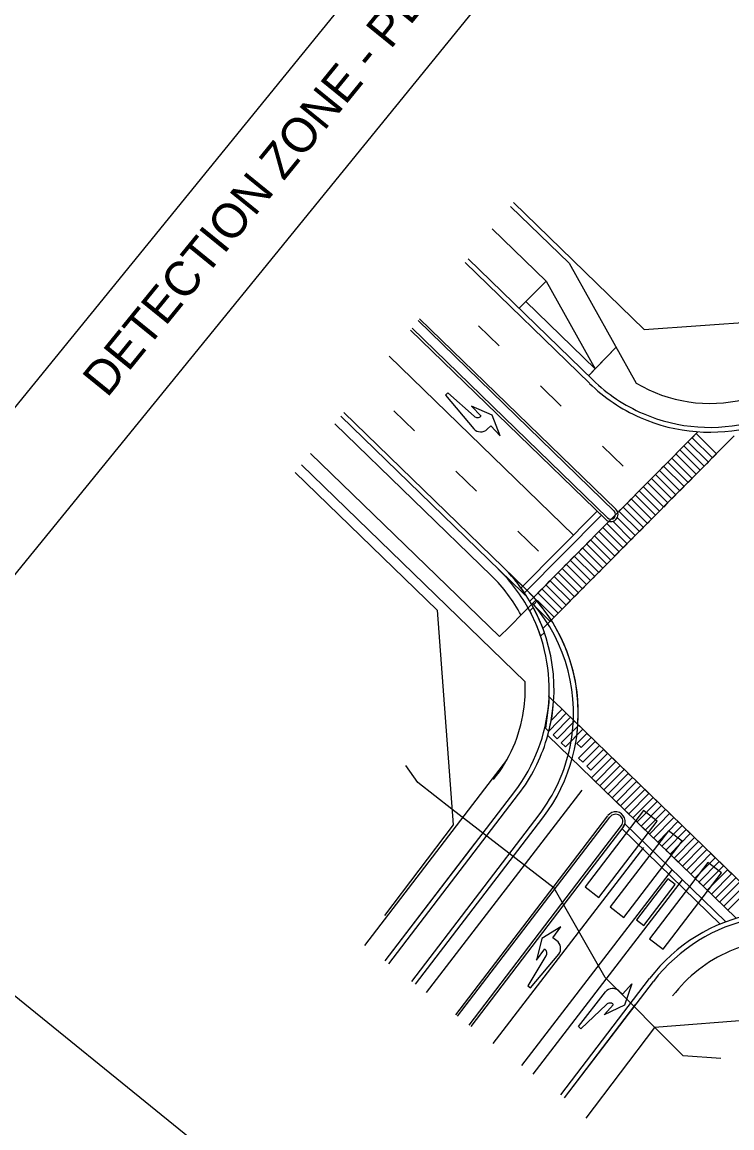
# Model space of a CAD drawing. Extents: x 592613 to 600223, y 4837996 to 4840103.
# Drawn here: x 592701.09 to 592719.57, y 4838932.93 to 4838961.75 of the extents above; entities that cross this region are included whole.
import ezdxf

# ---------------------------------------------------------------- set-up
doc = ezdxf.new("R2010")
doc.units = 0
for name, color, linetype in [('ENG_BORDER', 7, 'Continuous'), ('ENG_BUS-PAD', 7, 'Continuous'), ('ENG_CURB-BACK', 7, 'Continuous'), ('ENG_CURBSTOP', 7, 'Continuous'), ('ENG_EPAVT', 7, 'Continuous'), ('ENG_KILLSTRIP', 7, 'Continuous'), ('ENG_LANEWAY', 7, 'Continuous'), ('ENG_MULTI-TRAIL', 7, 'Continuous'), ('ENG_SH_RIPRAP', 7, 'Continuous'), ('ENG_SIDEWALK', 7, 'Continuous'), ('ENG_TITLEBLOCK', 7, 'Continuous'), ('ENG_TX_TITLEBLOCK', 7, 'Continuous'), ('Level 11', 7, 'Continuous'), ('Level 12', 7, 'Continuous'), ('PMK_LANE', 7, 'Continuous'), ('PMK_LANE_3-6', 7, 'Continuous'), ('ROW_ENG_ROW', 7, 'Continuous')]:
    doc.layers.add(name, color=color, linetype=linetype)

msp = doc.modelspace()

# ---------------------------------------------------------------- linework, layer by layer
at = {"layer": 'ENG_BORDER'}
msp.add_lwpolyline([(592658.479, 4838970.843), (592762.862, 4838886.033)], dxfattribs=at)
at = {"layer": 'ENG_BUS-PAD'}
for p, q in [((592714.73, 4838955.003), (592713.331, 4838956.363)), ((592714.026, 4838954.293), (592714.73, 4838955.003))]:
    msp.add_line(p, q, dxfattribs=at)
at = {"layer": 'ENG_CURB-BACK'}
for p, q in [((592715.946, 4838952.427), (592712.7, 4838955.581)), ((592716.329, 4838948.831), (592711.24, 4838953.775)), ((592716.504, 4838949.01), (592711.398, 4838953.971)), ((592714.119, 4838946.883), (592709.386, 4838951.481)), ((592710.54, 4838937.284), (592713.916, 4838941.704)), ((592711.236, 4838936.753), (592714.548, 4838941.09)), ((592715.454, 4838939.806), (592716.391, 4838941.033)), ((592715.672, 4838939.474), (592716.693, 4838940.811)), ((592712.428, 4838935.842), (592715.454, 4838939.806)), ((592712.726, 4838935.615), (592715.672, 4838939.473)), ((592715.21, 4838933.719), (592717.525, 4838936.751))]:
    msp.add_line(p, q, dxfattribs=at)
for centre, radius, start, end in [((592718.995, 4838955.565), 4.375, 246.6005, 322.6377), ((592718.995, 4838955.565), 4.375, 225.8289, 246.6005), ((592716.416, 4838948.921), 0.125, 315.8289, 45.8289), ((592716.416, 4838948.921), 0.125, 225.8289, 315.8289), ((592710.438, 4838944.359), 4.375, 27.9119, 45.8289), ((592710.438, 4838944.359), 4.125, 28.0452, 45.829), ((592711.07, 4838943.745), 4.375, 44.5335, 45.8289), ((592711.07, 4838943.745), 4.375, 348.3699, 40.8056), ((592710.438, 4838944.359), 4.375, 322.6377, 27.9119), ((592711.07, 4838943.745), 4.375, 322.6377, 348.3699), ((592716.541, 4838940.92), 0.187, 324.4115, 142.9443), ((592721.003, 4838934.096), 4.375, 60.4988, 142.6377)]:
    msp.add_arc(centre, radius, start, end, dxfattribs=at)
at = {"layer": 'ENG_CURBSTOP'}
for points in [[(592714.587, 4838945.747), (592714.686, 4838945.846), (592714.619, 4838946.023), (592714.563, 4838946.159), (592714.507, 4838946.281), (592714.426, 4838946.443), (592714.398, 4838946.498), (592714.398, 4838946.498), (592714.307, 4838946.406), (592714.34, 4838946.327), (592714.459, 4838946.083), (592714.545, 4838945.869)], [(592714.713, 4838943.355), (592714.802, 4838943.268), (592714.885, 4838943.667), (592714.918, 4838943.936), (592714.926, 4838944.057), (592714.926, 4838944.057), (592714.799, 4838944.18), (592714.8, 4838944.194), (592714.8, 4838944.017), (592714.78, 4838943.818)]]:
    msp.add_lwpolyline(points, close=True, dxfattribs=at)
at = {"layer": 'ENG_EPAVT'}
for p, q in [((592715.859, 4838952.338), (592712.621, 4838955.484)), ((592716.547, 4838949.055), (592711.437, 4838954.019)), ((592716.286, 4838948.786), (592711.2, 4838953.727)), ((592714.206, 4838946.973), (592709.465, 4838951.579)), ((592713.517, 4838945.737), (592708.599, 4838950.508)), ((592713.766, 4838945.986), (592714.144, 4838946.366)), ((592713.517, 4838945.737), (592713.766, 4838945.986)), ((592710.64, 4838937.208), (592714.015, 4838941.628)), ((592711.335, 4838936.677), (592714.647, 4838941.014)), ((592715.416, 4838939.859), (592716.341, 4838941.07)), ((592715.709, 4838939.418), (592716.735, 4838940.763)), ((592712.378, 4838935.88), (592715.415, 4838939.857)), ((592712.776, 4838935.577), (592715.709, 4838939.418)), ((592715.111, 4838933.794), (592717.426, 4838936.827))]:
    msp.add_line(p, q, dxfattribs=at)
for centre, radius, start, end in [((592718.995, 4838955.565), 4.5, 246.1583, 322.6377), ((592718.995, 4838955.565), 4.5, 225.8289, 246.1583), ((592716.416, 4838948.921), 0.188, 315.8289, 45.8289), ((592716.416, 4838948.921), 0.188, 225.8289, 315.8289), ((592710.438, 4838944.359), 4.5, 33.0068, 45.8289), ((592711.07, 4838943.745), 4.5, 322.6377, 51.4479), ((592711.07, 4838943.745), 4.5, 349.35, 45.8289), ((592710.438, 4838944.359), 4.5, 343.3725, 33.0068), ((592710.438, 4838944.359), 4.5, 322.6377, 343.3725), ((592716.541, 4838940.92), 0.25, 321.1016, 142.9443), ((592716.54, 4838940.92), 0.25, 320.9502, 142.7929), ((592721.003, 4838934.096), 4.5, 60.2342, 142.6377)]:
    msp.add_arc(centre, radius, start, end, dxfattribs=at)
at = {"layer": 'ENG_KILLSTRIP'}
for p, q in [((592716.01, 4838952.714), (592714.202, 4838954.47)), ((592713.313, 4838947.318), (592709.228, 4838951.286))]:
    msp.add_line(p, q, dxfattribs=at)
at = {"layer": 'ENG_LANEWAY'}
for p, q in [((592711.621, 4838936.463), (592715.671, 4838941.738)), ((592713.356, 4838935.131), (592717.28, 4838940.242)), ((592714.1, 4838934.56), (592718.024, 4838939.671)), ((592714.397, 4838934.331), (592718.285, 4838939.396))]:
    msp.add_line(p, q, dxfattribs=at)
at = {"layer": 'ENG_MULTI-TRAIL'}
for p, q in [((592715.331, 4838955.465), (592713.804, 4838956.948)), ((592714.73, 4838955.003), (592716.01, 4838952.714))]:
    msp.add_line(p, q, dxfattribs=at)
at = {"layer": 'ENG_SH_RIPRAP'}
msp.add_lwpolyline([(592719.284, 4838934.743), (592718.297, 4838934.816), (592716.266, 4838936.852), (592714.944, 4838939.184), (592712.281, 4838941.242), (592711.39, 4838941.933), (592711.082, 4838942.376)], dxfattribs=at)
at = {"layer": 'ENG_SIDEWALK'}
for p, q in [((592715.331, 4838955.465), (592717.077, 4838952.343)), ((592716.555, 4838953.276), (592715.836, 4838952.535)), ((592716.01, 4838952.714), (592716.555, 4838953.276)), ((592715.838, 4838952.533), (592716.01, 4838952.714)), ((592714.183, 4838944.555), (592708.36, 4838950.212)), ((592713.989, 4838946.208), (592714.372, 4838946.595)), ((592714.372, 4838946.595), (592714.479, 4838946.702)), ((592713.334, 4838942.033), (592713.707, 4838942.521)), ((592710.015, 4838937.685), (592713.334, 4838942.033)), ((592710.54, 4838937.284), (592712.885, 4838940.355)), ((592715.21, 4838933.719), (592717.07, 4838936.154))]:
    msp.add_line(p, q, dxfattribs=at)
for centre, start, end in [((592718.995, 4838955.565), 239.233, 283.8878), ((592710.438, 4838944.359), 351.4856, 2.9955), ((592710.438, 4838944.359), 321.332, 351.4856), ((592721.003, 4838934.096), 90.4558, 113.33), ((592721.003, 4838934.096), 113.33, 142.6377)]:
    msp.add_arc(centre, 3.75, start, end, dxfattribs=at)
at = {"layer": 'ENG_TITLEBLOCK'}
msp.add_line((592695.53, 4838940.74), (592723.069, 4838974.634), dxfattribs=at)
msp.add_line((592695.53, 4838940.74), (592723.069, 4838974.634), dxfattribs=at)
msp.add_lwpolyline([(592693.395, 4838942.474), (592720.934, 4838976.368)], dxfattribs=at)
at = {"layer": 'Level 11'}
for p, q in [((592717.269, 4838941.201), (592715.75, 4838939.215)), ((592717.626, 4838940.927), (592717.269, 4838941.201)), ((592716.107, 4838938.942), (592717.626, 4838940.927)), ((592717.914, 4838940.679), (592716.396, 4838938.693)), ((592718.272, 4838940.405), (592717.914, 4838940.679)), ((592716.753, 4838938.42), (592718.272, 4838940.405)), ((592718.94, 4838939.851), (592717.421, 4838937.865)), ((592719.297, 4838939.577), (592718.94, 4838939.851)), ((592717.902, 4838939.421), (592717.088, 4838938.357)), ((592717.778, 4838937.591), (592719.297, 4838939.577)), ((592718.093, 4838939.274), (592717.902, 4838939.421)), ((592715.75, 4838939.215), (592716.107, 4838938.942)), ((592717.28, 4838938.211), (592718.093, 4838939.274)), ((592716.396, 4838938.693), (592716.753, 4838938.42)), ((592717.088, 4838938.357), (592717.28, 4838938.211)), ((592717.421, 4838937.865), (592717.778, 4838937.591))]:
    msp.add_line(p, q, dxfattribs=at)
at = {"layer": 'Level 12'}
for p, q in [((592712.174, 4838952.089), (592712.108, 4838952.025)), ((592712.108, 4838952.025), (592712.846, 4838951.149)), ((592712.858, 4838951.485), (592712.174, 4838952.089)), ((592713.326, 4838951.512), (592712.792, 4838951.745)), ((592712.792, 4838951.745), (592713.041, 4838951.486)), ((592713.537, 4838950.969), (592713.326, 4838951.512)), ((592713.2, 4838951.142), (592713.289, 4838951.228)), ((592713.289, 4838951.228), (592713.537, 4838950.969)), ((592715.118, 4838938.176), (592714.62, 4838937.873)), ((592714.907, 4838937.886), (592715.118, 4838938.176)), ((592714.62, 4838937.873), (592714.484, 4838937.307)), ((592715.007, 4838937.813), (592714.907, 4838937.886)), ((592714.728, 4838937.417), (592714.253, 4838936.638)), ((592714.327, 4838936.584), (592715.061, 4838937.464)), ((592714.484, 4838937.307), (592714.695, 4838937.596)), ((592714.253, 4838936.638), (592714.327, 4838936.584)), ((592715.571, 4838935.579), (592716.276, 4838936.482)), ((592716.629, 4838936.502), (592716.721, 4838936.419)), ((592716.721, 4838936.419), (592716.96, 4838936.687)), ((592716.96, 4838936.687), (592716.769, 4838936.136)), ((592716.301, 4838936.147), (592715.639, 4838935.518)), ((592716.244, 4838935.884), (592716.483, 4838936.152)), ((592716.769, 4838936.136), (592716.244, 4838935.884)), ((592715.639, 4838935.518), (592715.571, 4838935.579))]:
    msp.add_line(p, q, dxfattribs=at)
for centre, radius, start, end in [((592712.949, 4838951.571), 0.125, 223.8199, 313.8436), ((592713.026, 4838951.322), 0.25, 223.8262, 313.8484), ((592714.859, 4838937.611), 0.25, 323.8506, 53.8728), ((592714.627, 4838937.491), 0.125, 323.8443, 53.8679), ((592716.462, 4838936.315), 0.25, 48.242, 138.2642), ((592716.394, 4838936.063), 0.125, 48.2469, 138.2706)]:
    msp.add_arc(centre, radius, start, end, dxfattribs=at)
at = {"layer": 'PMK_LANE'}
for p, q in [((592715.446, 4838948.382), (592710.648, 4838953.043)), ((592718.684, 4838951.076), (592714.304, 4838946.663)), ((592719.631, 4838950.965), (592714.649, 4838945.946)), ((592718.636, 4838951.028), (592718.531, 4838950.921)), ((592718.531, 4838950.921), (592719.062, 4838950.392)), ((592719.167, 4838950.498), (592718.636, 4838951.028)), ((592718.214, 4838950.602), (592718.108, 4838950.496)), ((592718.744, 4838950.072), (592718.214, 4838950.602)), ((592718.425, 4838950.815), (592718.319, 4838950.708)), ((592718.319, 4838950.708), (592718.85, 4838950.179)), ((592718.956, 4838950.285), (592718.425, 4838950.815)), ((592718.002, 4838950.389), (592717.897, 4838950.283)), ((592718.533, 4838949.859), (592718.002, 4838950.389)), ((592718.108, 4838950.496), (592718.639, 4838949.966)), ((592719.062, 4838950.392), (592719.167, 4838950.498)), ((592717.791, 4838950.176), (592717.685, 4838950.07)), ((592717.685, 4838950.07), (592718.216, 4838949.54)), ((592718.322, 4838949.646), (592717.791, 4838950.176)), ((592717.897, 4838950.283), (592718.427, 4838949.753)), ((592718.639, 4838949.966), (592718.744, 4838950.072)), ((592718.85, 4838950.179), (592718.956, 4838950.285)), ((592717.899, 4838949.22), (592717.368, 4838949.75)), ((592717.58, 4838949.963), (592717.474, 4838949.857)), ((592717.474, 4838949.857), (592718.005, 4838949.327)), ((592718.11, 4838949.433), (592717.58, 4838949.963)), ((592718.427, 4838949.753), (592718.533, 4838949.859)), ((592717.157, 4838949.537), (592717.051, 4838949.431)), ((592717.051, 4838949.431), (592717.582, 4838948.901)), ((592717.688, 4838949.008), (592717.157, 4838949.537)), ((592717.263, 4838949.644), (592717.793, 4838949.114)), ((592718.005, 4838949.327), (592718.11, 4838949.433)), ((592718.216, 4838949.54), (592718.322, 4838949.646)), ((592716.946, 4838949.325), (592716.84, 4838949.218)), ((592716.84, 4838949.218), (592717.371, 4838948.688)), ((592717.476, 4838948.795), (592716.946, 4838949.325)), ((592717.793, 4838949.114), (592717.899, 4838949.22)), ((592716.063, 4838949.003), (592714.079, 4838947.004)), ((592716.17, 4838948.898), (592714.166, 4838946.88)), ((592716.734, 4838949.112), (592716.629, 4838949.005)), ((592716.629, 4838949.005), (592717.159, 4838948.475)), ((592717.265, 4838948.582), (592716.734, 4838949.112)), ((592717.582, 4838948.901), (592717.688, 4838949.008)), ((592716.312, 4838948.686), (592716.206, 4838948.579)), ((592716.206, 4838948.579), (592716.737, 4838948.049)), ((592716.842, 4838948.156), (592716.312, 4838948.686)), ((592716.591, 4838948.831), (592716.485, 4838948.724)), ((592716.485, 4838948.724), (592716.948, 4838948.262)), ((592717.054, 4838948.369), (592716.591, 4838948.831)), ((592717.159, 4838948.475), (592717.265, 4838948.582)), ((592717.371, 4838948.688), (592717.476, 4838948.795)), ((592716.1, 4838948.473), (592715.994, 4838948.366)), ((592715.994, 4838948.366), (592716.525, 4838947.837)), ((592716.631, 4838947.943), (592716.1, 4838948.473)), ((592716.948, 4838948.262), (592717.054, 4838948.369)), ((592715.677, 4838948.047), (592715.572, 4838947.941)), ((592716.208, 4838947.517), (592715.677, 4838948.047)), ((592715.889, 4838948.26), (592715.783, 4838948.154)), ((592715.783, 4838948.154), (592716.314, 4838947.624)), ((592716.42, 4838947.73), (592715.889, 4838948.26)), ((592716.737, 4838948.049), (592716.842, 4838948.156)), ((592715.466, 4838947.834), (592715.36, 4838947.728)), ((592715.36, 4838947.728), (592715.891, 4838947.198)), ((592715.997, 4838947.304), (592715.466, 4838947.834)), ((592715.572, 4838947.941), (592716.103, 4838947.411)), ((592716.314, 4838947.624), (592716.42, 4838947.73)), ((592716.525, 4838947.837), (592716.631, 4838947.943)), ((592715.255, 4838947.621), (592715.149, 4838947.515)), ((592715.149, 4838947.515), (592715.68, 4838946.985)), ((592715.786, 4838947.091), (592715.255, 4838947.621)), ((592716.103, 4838947.411), (592716.208, 4838947.517)), ((592714.832, 4838947.195), (592714.726, 4838947.089)), ((592715.363, 4838946.666), (592714.832, 4838947.195)), ((592715.043, 4838947.408), (592714.938, 4838947.302)), ((592714.938, 4838947.302), (592715.469, 4838946.772)), ((592715.574, 4838946.878), (592715.043, 4838947.408)), ((592715.891, 4838947.198), (592715.997, 4838947.304)), ((592714.621, 4838946.983), (592714.515, 4838946.876)), ((592714.515, 4838946.876), (592715.046, 4838946.346)), ((592715.151, 4838946.453), (592714.621, 4838946.983)), ((592714.726, 4838947.089), (592715.257, 4838946.559)), ((592715.469, 4838946.772), (592715.574, 4838946.878)), ((592715.68, 4838946.985), (592715.786, 4838947.091)), ((592714.505, 4838946.674), (592714.399, 4838946.568)), ((592714.399, 4838946.568), (592714.834, 4838946.133)), ((592714.94, 4838946.24), (592714.505, 4838946.674)), ((592715.257, 4838946.559), (592715.363, 4838946.666)), ((592715.046, 4838946.346), (592715.151, 4838946.453)), ((592714.834, 4838946.133), (592714.94, 4838946.24)), ((592714.928, 4838944.059), (592720.415, 4838938.73)), ((592714.808, 4838943.283), (592715.258, 4838943.739)), ((592715.15, 4838943.843), (592714.866, 4838943.555)), ((592715.258, 4838943.739), (592715.15, 4838943.843)), ((592715.365, 4838943.634), (592714.913, 4838943.176)), ((592715.021, 4838943.072), (592715.473, 4838943.53)), ((592715.581, 4838943.425), (592715.127, 4838942.966)), ((592715.473, 4838943.53), (592715.365, 4838943.634)), ((592715.688, 4838943.321), (592715.581, 4838943.425)), ((592714.776, 4838943.161), (592719.681, 4838938.398)), ((592714.913, 4838943.176), (592715.021, 4838943.072)), ((592715.235, 4838942.861), (592715.688, 4838943.321)), ((592715.796, 4838943.216), (592715.532, 4838942.949)), ((592715.64, 4838942.845), (592715.903, 4838943.112)), ((592715.903, 4838943.112), (592715.796, 4838943.216)), ((592715.127, 4838942.966), (592715.235, 4838942.861)), ((592715.532, 4838942.949), (592715.64, 4838942.845)), ((592716.011, 4838943.007), (592715.577, 4838942.568)), ((592715.685, 4838942.463), (592716.119, 4838942.903)), ((592716.119, 4838942.903), (592716.011, 4838943.007)), ((592715.577, 4838942.568), (592715.685, 4838942.463)), ((592716.226, 4838942.798), (592715.791, 4838942.358)), ((592715.899, 4838942.253), (592716.334, 4838942.694)), ((592716.441, 4838942.589), (592715.915, 4838942.055)), ((592716.334, 4838942.694), (592716.226, 4838942.798)), ((592716.549, 4838942.485), (592716.441, 4838942.589)), ((592715.791, 4838942.358), (592715.899, 4838942.253)), ((592716.022, 4838941.951), (592716.549, 4838942.485)), ((592716.657, 4838942.38), (592716.13, 4838941.846)), ((592716.237, 4838941.742), (592716.764, 4838942.276)), ((592716.764, 4838942.276), (592716.657, 4838942.38)), ((592715.915, 4838942.055), (592716.022, 4838941.951)), ((592716.872, 4838942.171), (592716.345, 4838941.637)), ((592716.453, 4838941.533), (592716.98, 4838942.066)), ((592717.087, 4838941.962), (592716.56, 4838941.428)), ((592716.98, 4838942.066), (592716.872, 4838942.171)), ((592717.195, 4838941.857), (592717.087, 4838941.962)), ((592716.13, 4838941.846), (592716.237, 4838941.742)), ((592716.668, 4838941.324), (592717.195, 4838941.857)), ((592717.302, 4838941.753), (592716.775, 4838941.219)), ((592717.41, 4838941.648), (592717.302, 4838941.753)), ((592716.345, 4838941.637), (592716.453, 4838941.533)), ((592716.56, 4838941.428), (592716.668, 4838941.324)), ((592716.883, 4838941.115), (592717.41, 4838941.648)), ((592717.518, 4838941.544), (592716.991, 4838941.01)), ((592717.098, 4838940.906), (592717.625, 4838941.439)), ((592717.625, 4838941.439), (592717.518, 4838941.544)), ((592716.775, 4838941.219), (592716.883, 4838941.115)), ((592717.733, 4838941.335), (592717.206, 4838940.801)), ((592717.313, 4838940.697), (592717.84, 4838941.23)), ((592717.948, 4838941.126), (592717.421, 4838940.592)), ((592717.84, 4838941.23), (592717.733, 4838941.335)), ((592718.056, 4838941.021), (592717.948, 4838941.126)), ((592716.784, 4838940.862), (592719.415, 4838938.307)), ((592716.991, 4838941.01), (592717.098, 4838940.906)), ((592717.206, 4838940.801), (592717.313, 4838940.697)), ((592717.529, 4838940.488), (592718.056, 4838941.021)), ((592718.163, 4838940.917), (592717.636, 4838940.383)), ((592717.744, 4838940.279), (592718.271, 4838940.812)), ((592718.271, 4838940.812), (592718.163, 4838940.917)), ((592716.708, 4838940.727), (592719.263, 4838938.246)), ((592717.421, 4838940.592), (592717.529, 4838940.488)), ((592718.378, 4838940.708), (592717.852, 4838940.174)), ((592717.959, 4838940.07), (592718.486, 4838940.603)), ((592718.594, 4838940.499), (592718.067, 4838939.965)), ((592718.486, 4838940.603), (592718.378, 4838940.708)), ((592718.701, 4838940.394), (592718.594, 4838940.499)), ((592717.636, 4838940.383), (592717.744, 4838940.279)), ((592718.174, 4838939.861), (592718.701, 4838940.394)), ((592718.809, 4838940.29), (592718.282, 4838939.756)), ((592718.917, 4838940.185), (592718.809, 4838940.29)), ((592717.852, 4838940.174), (592717.959, 4838940.07)), ((592718.067, 4838939.965), (592718.174, 4838939.861)), ((592718.39, 4838939.652), (592718.917, 4838940.185)), ((592719.024, 4838940.081), (592718.497, 4838939.547)), ((592718.605, 4838939.443), (592719.132, 4838939.976)), ((592719.132, 4838939.976), (592719.024, 4838940.081)), ((592718.282, 4838939.756), (592718.39, 4838939.652)), ((592719.239, 4838939.872), (592718.712, 4838939.338)), ((592718.82, 4838939.234), (592719.347, 4838939.767)), ((592719.455, 4838939.663), (592718.928, 4838939.129)), ((592719.347, 4838939.767), (592719.239, 4838939.872)), ((592719.562, 4838939.558), (592719.455, 4838939.663)), ((592718.497, 4838939.547), (592718.605, 4838939.443)), ((592719.035, 4838939.025), (592719.562, 4838939.558)), ((592719.67, 4838939.454), (592719.143, 4838938.92)), ((592719.25, 4838938.816), (592719.777, 4838939.349)), ((592718.712, 4838939.338), (592718.82, 4838939.234)), ((592718.928, 4838939.129), (592719.035, 4838939.025)), ((592719.885, 4838939.245), (592719.358, 4838938.711)), ((592719.466, 4838938.607), (592719.993, 4838939.14)), ((592719.143, 4838938.92), (592719.25, 4838938.816)), ((592719.358, 4838938.711), (592719.466, 4838938.607))]:
    msp.add_line(p, q, dxfattribs=at)
msp.add_lwpolyline([(592717.368, 4838949.75), (592717.274, 4838949.656), (592717.263, 4838949.644)], dxfattribs=at)
for points in [[(592714.079, 4838947.004), (592716.063, 4838949.003), (592716.17, 4838948.898), (592714.166, 4838946.88)], [(592716.708, 4838940.727), (592716.784, 4838940.862), (592719.415, 4838938.307), (592719.263, 4838938.246)]]:
    msp.add_lwpolyline(points, close=True, dxfattribs=at)
msp.add_arc((592710.438, 4838944.359), 4.5, 346.1571, 349.7059, dxfattribs=at)
at = {"layer": 'PMK_LANE_3-6'}
for p, q in [((592713.509, 4838953.314), (592712.971, 4838953.837)), ((592715.122, 4838951.746), (592714.584, 4838952.269)), ((592711.307, 4838951.096), (592710.769, 4838951.619)), ((592716.736, 4838950.178), (592716.198, 4838950.701)), ((592712.921, 4838949.528), (592712.383, 4838950.051)), ((592714.535, 4838947.96), (592713.997, 4838948.483))]:
    msp.add_line(p, q, dxfattribs=at)
at = {"layer": 'ROW_ENG_ROW'}
for p, q in [((592717.284, 4838953.742), (592713.883, 4838957.046)), ((592717.284, 4838953.742), (592722.233, 4838954.089)), ((592711.897, 4838946.428), (592708.202, 4838950.017)), ((592711.897, 4838946.428), (592712.311, 4838940.836)), ((592712.311, 4838940.836), (592710.526, 4838938.471)), ((592722.682, 4838935.95), (592717.554, 4838935.554)), ((592717.554, 4838935.554), (592715.77, 4838933.189))]:
    msp.add_line(p, q, dxfattribs=at)

# ---------------------------------------------------------------- texts
at = {"layer": 'ENG_TX_TITLEBLOCK'}
msp.add_text('DETECTION ZONE - PLAN VIEW', height=0.9, rotation=50.9062, dxfattribs=at).set_placement((592703.301, 4838951.94))

doc.saveas('drawing.dxf')
